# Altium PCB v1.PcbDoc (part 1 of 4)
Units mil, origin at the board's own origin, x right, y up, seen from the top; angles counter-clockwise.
Board outline 4875 x 2022 mil, 4 copper layers (Top Layer, Signal Layer 1, Signal Layer 2, Bottom Layer), stack 64.834 mil thick; 432 components, 288 nets, 1177 pads, 637 vias.
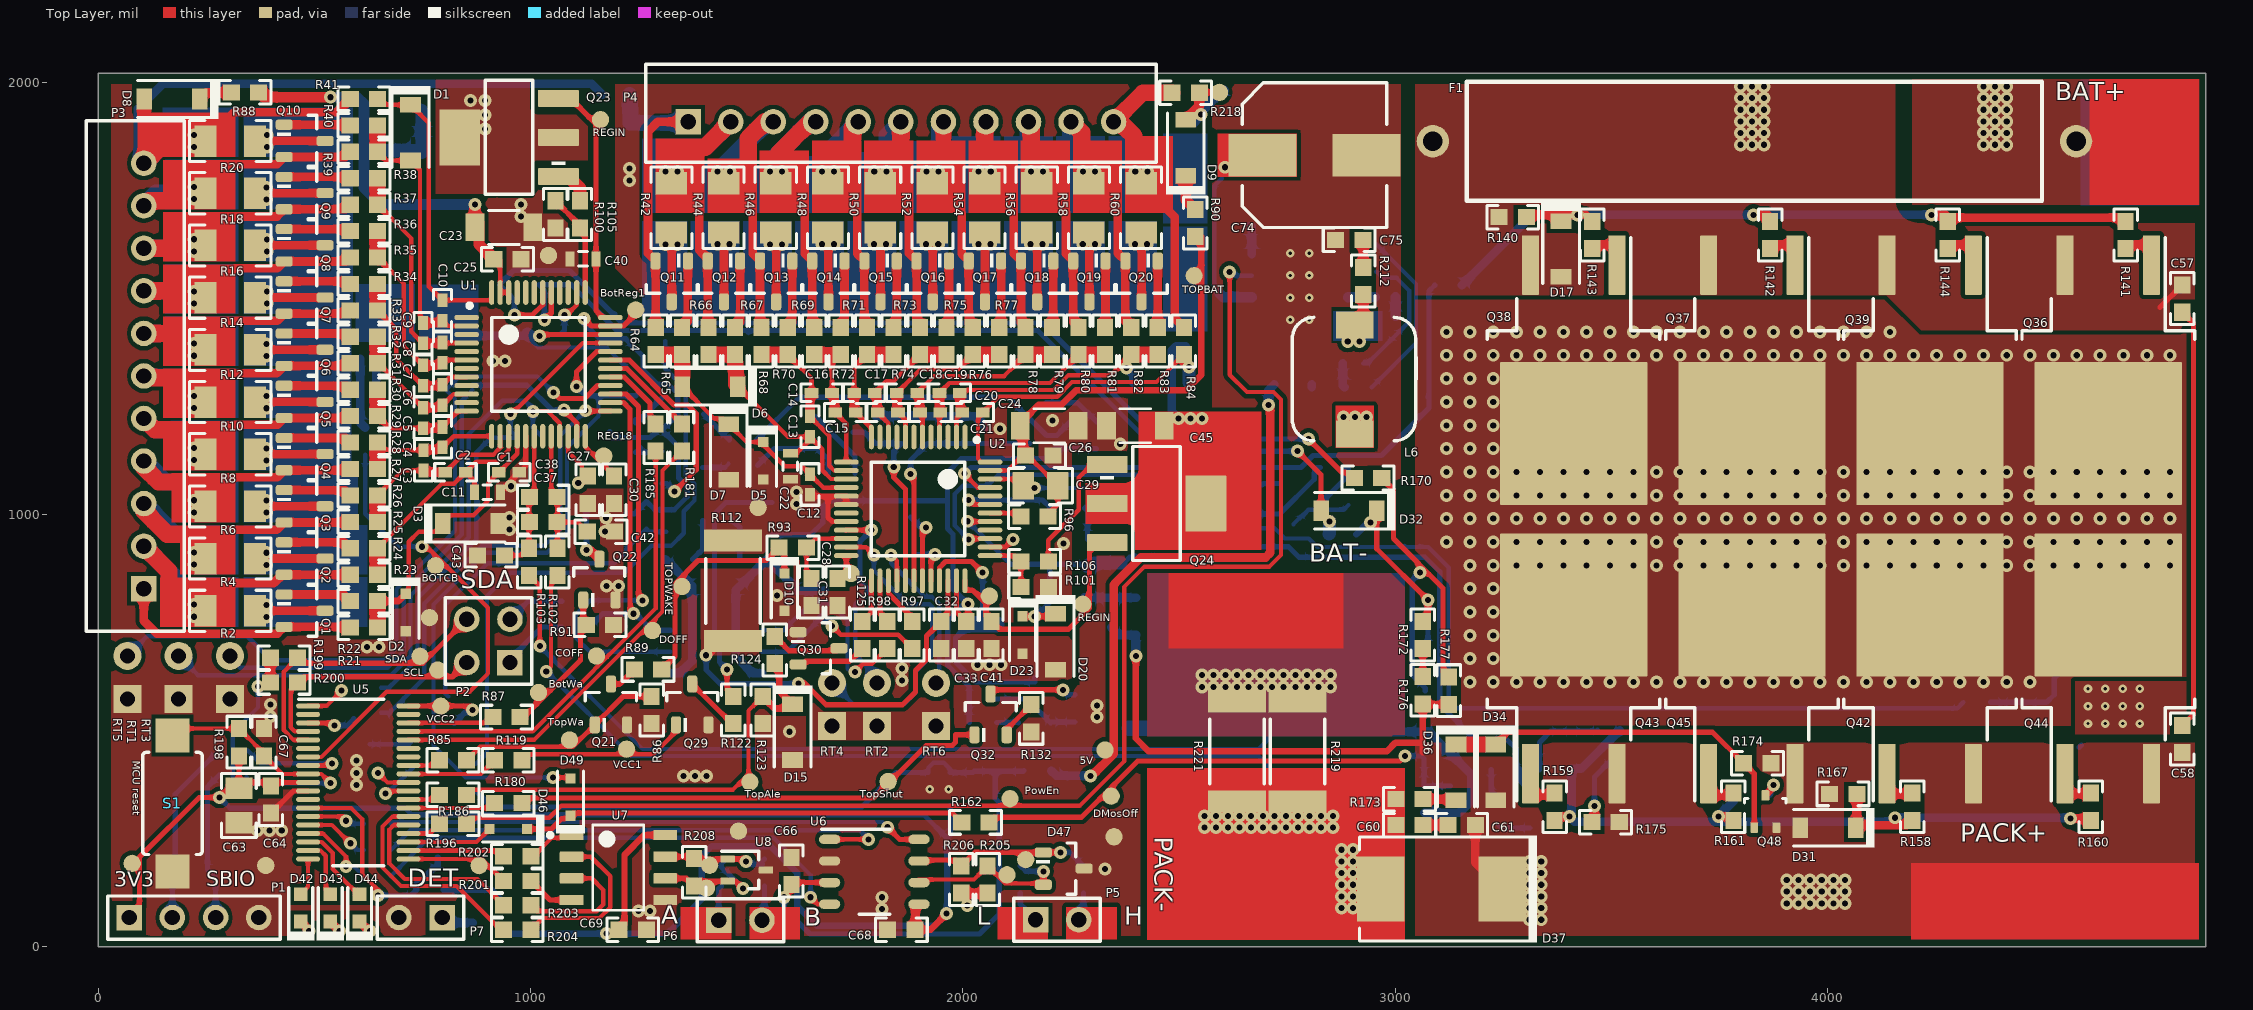
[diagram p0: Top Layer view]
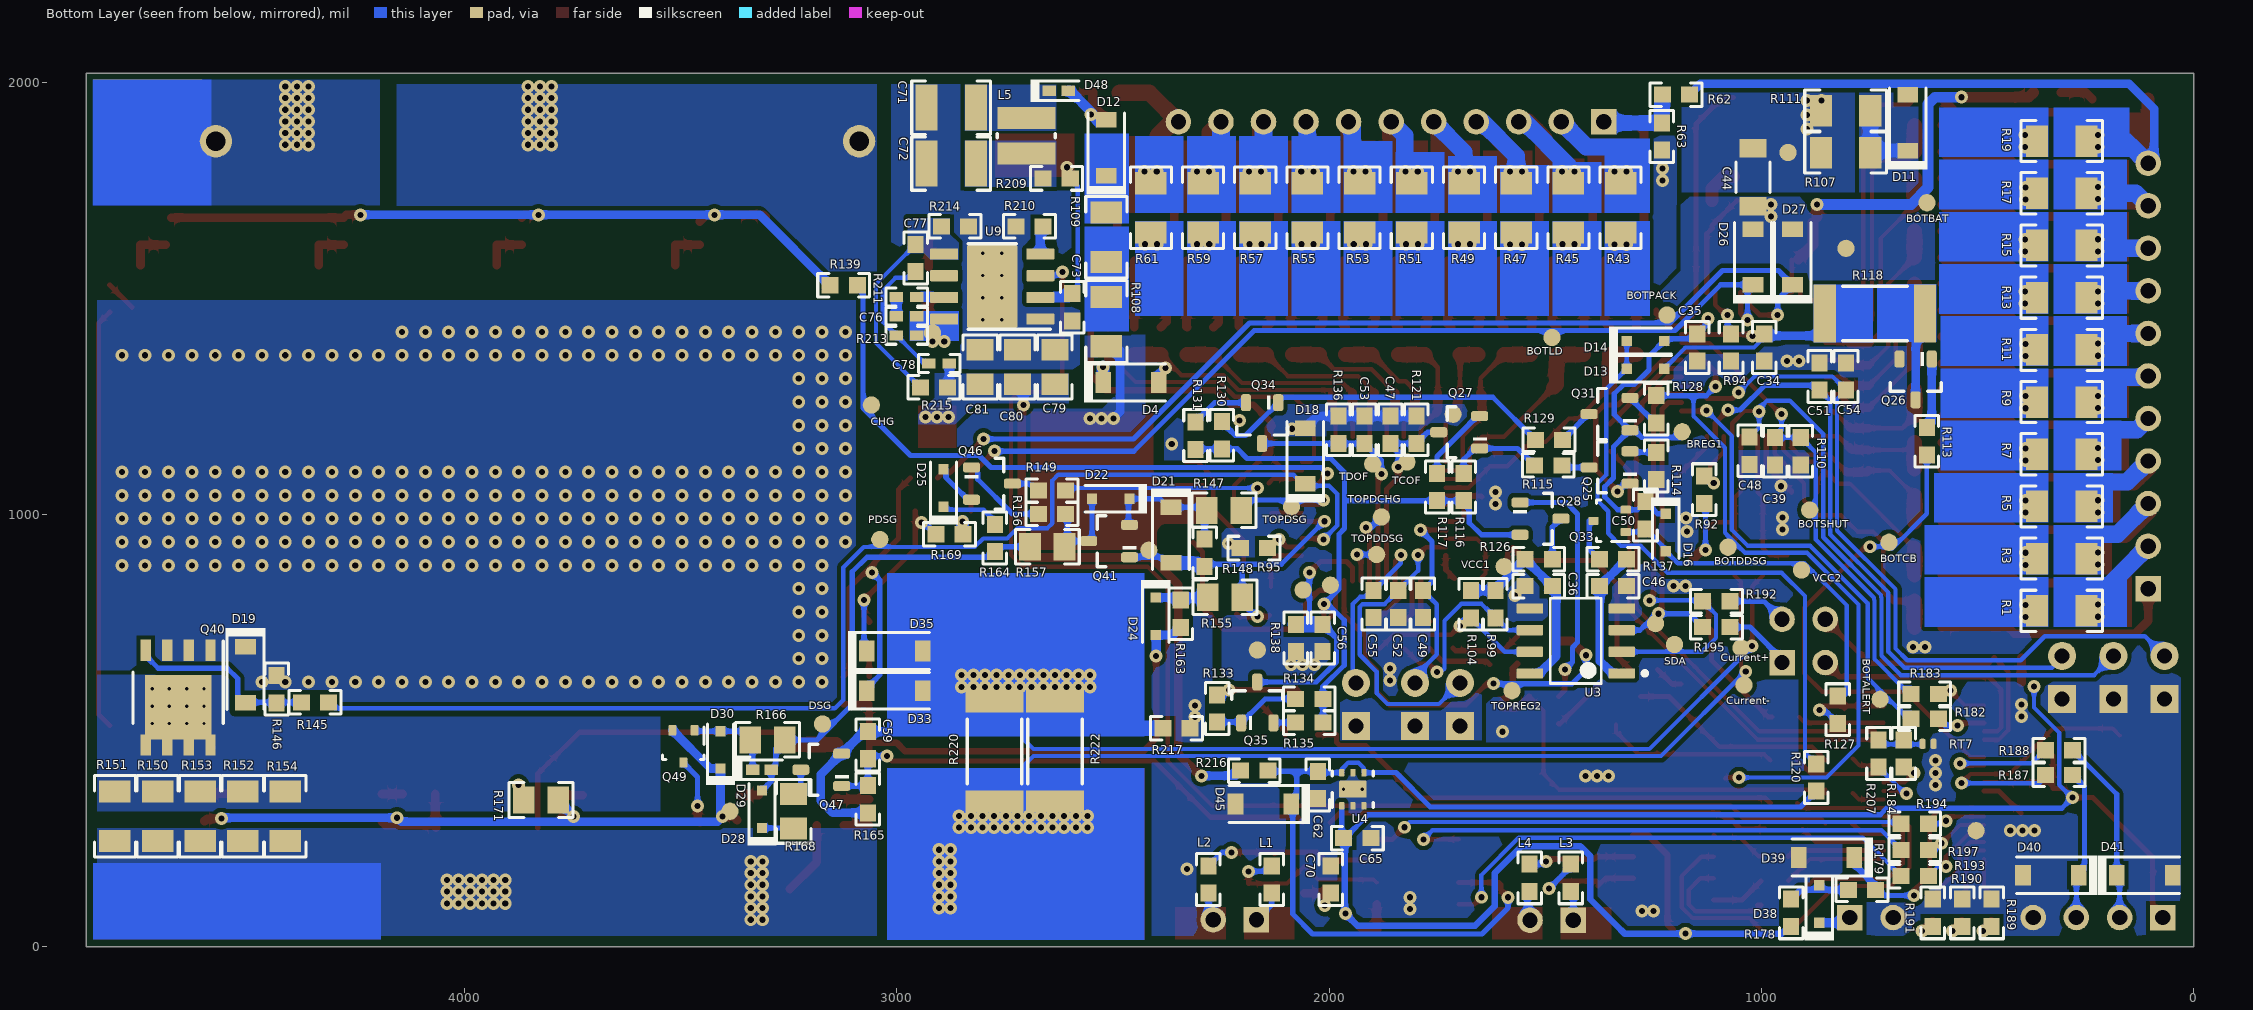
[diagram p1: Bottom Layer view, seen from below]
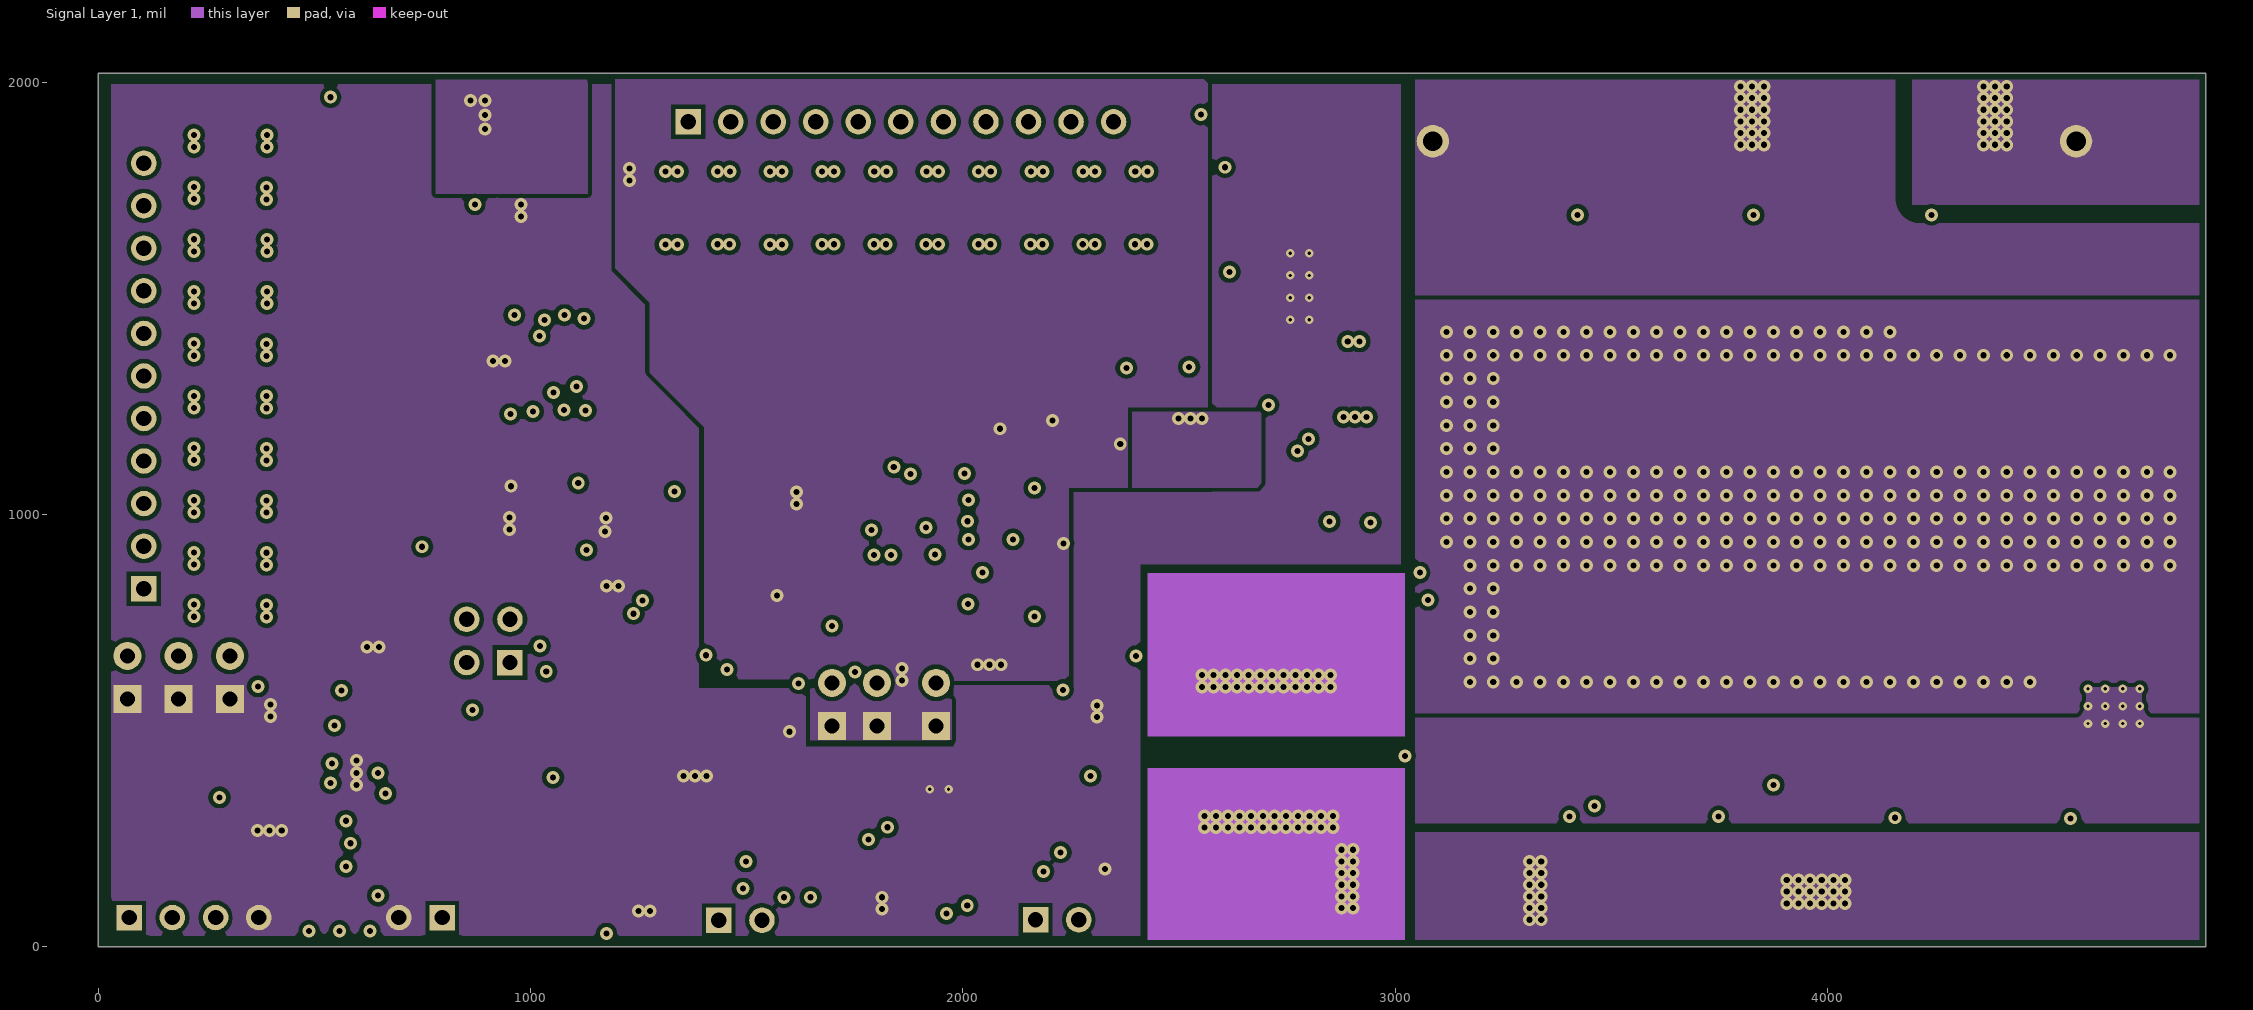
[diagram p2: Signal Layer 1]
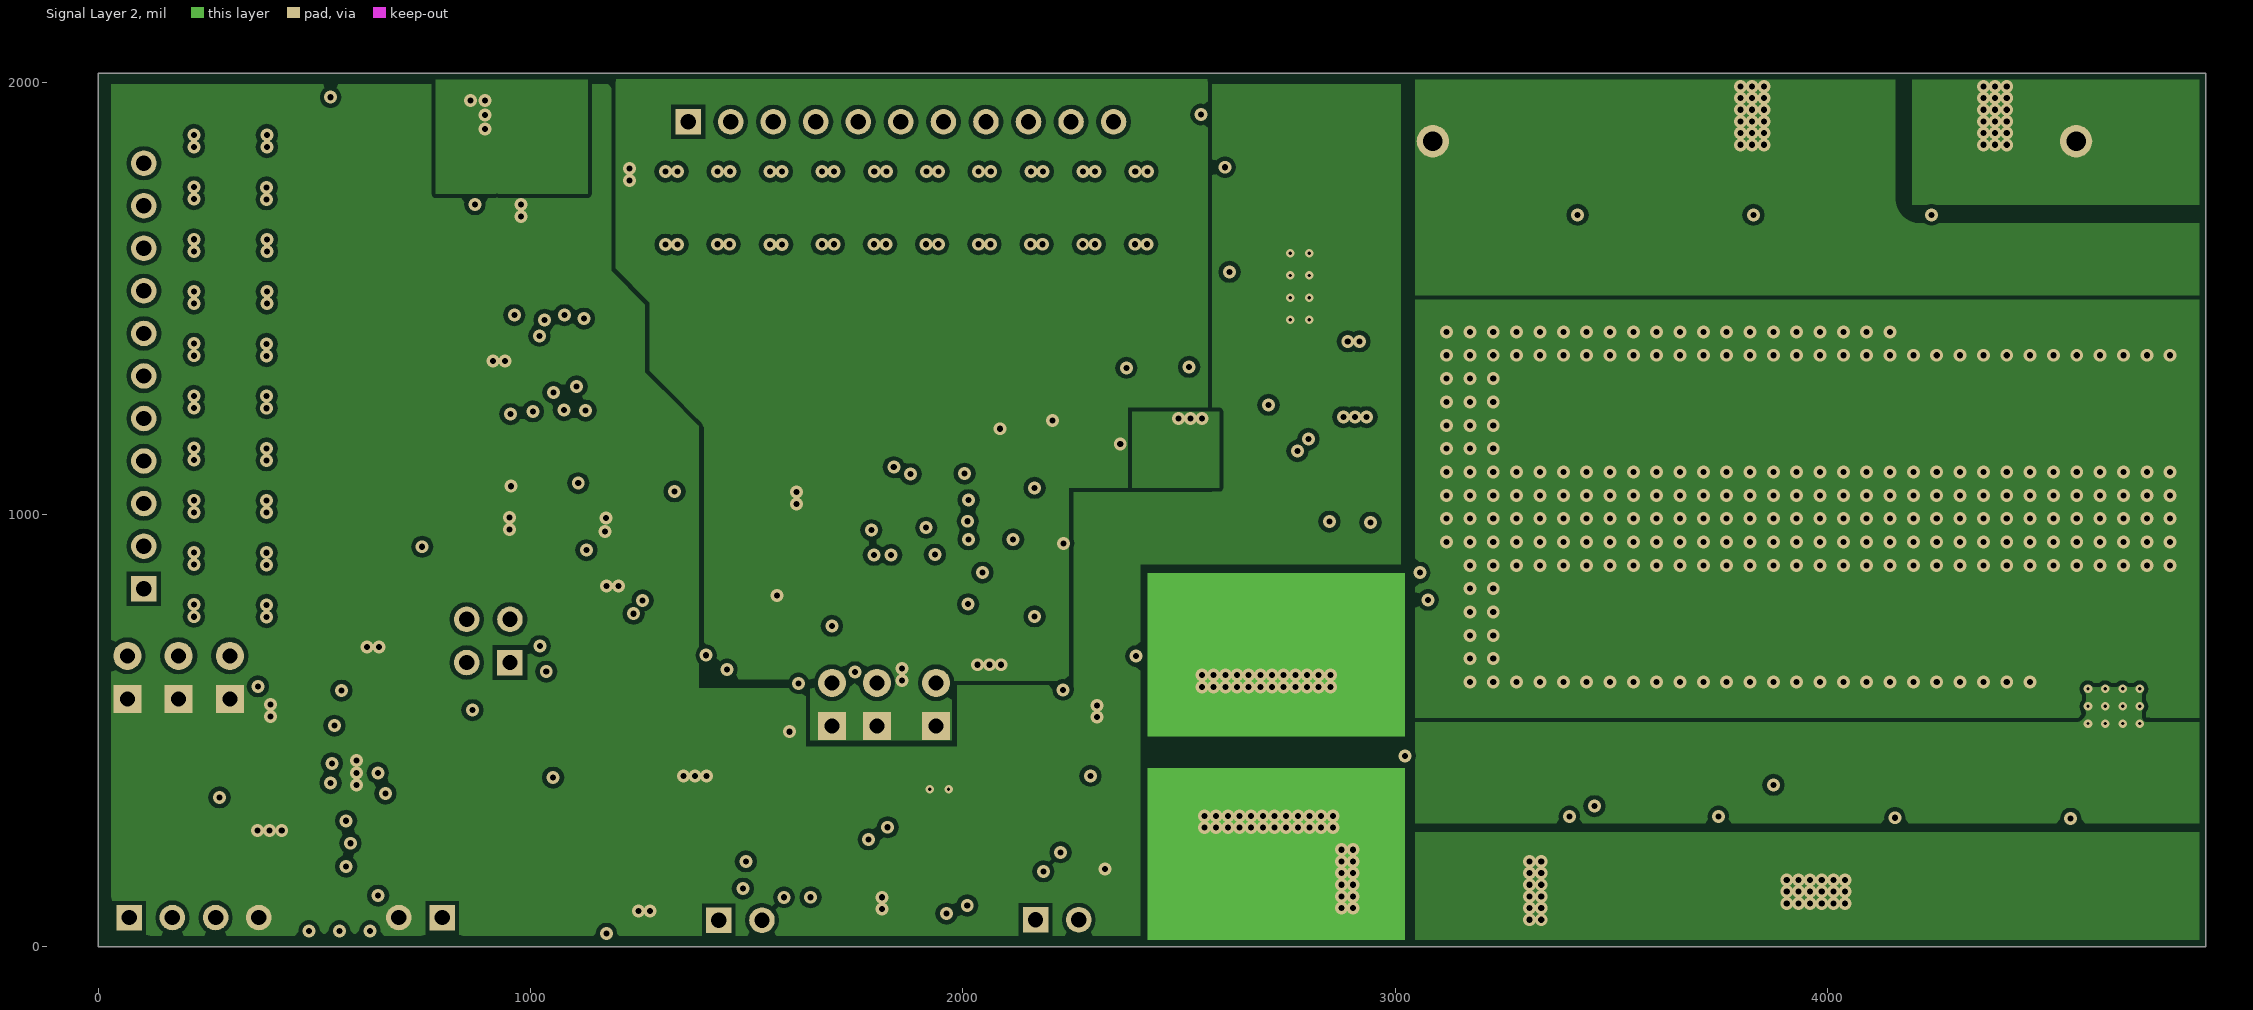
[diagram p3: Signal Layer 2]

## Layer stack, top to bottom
Top Solder: solder mask 0.4, Solder Resist, Dk 3.5
Top Layer: signal copper 1.4
Dielectric1: core 59.2, FR-4, Dk 4.8
Signal Layer 1: signal copper 1.417
Signal Layer 2: signal copper 1.417
Bottom Layer: signal copper 1.4
Bottom Solder: solder mask 0.4, Solder Resist, Dk 3.5

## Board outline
0,0 0,2022 4875,2022 4875,0

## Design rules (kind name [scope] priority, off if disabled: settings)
AcuteAngle [All] p1: minimum=4.50000000000000E+0001 checktracksonly=FALSE
AssemblyTestPointUsage [All] p1: valid=2
BoardOutlineClearance BoardOutlineClearance_MountingHoles [OnCopper and InComponentClass('Mounting Holes')] p1: gap=40 ignorepadtopadclearanceinfootprint=FALSE
BoardOutlineClearance BoardOutlineClearance_Poly [OnCopper and IsPoly] p2: gap=25 ignorepadtopadclearanceinfootprint=FALSE
BoardOutlineClearance [OnCopper and Not InComponentClass('Logo') and not InComponentClass('FiducialMark') and not InRegion(1000,500,4000,800) and not InPoly] p3 off: gap=75 ignorepadtopadclearanceinfootprint=FALSE
Clearance Clearance_Keepouts [((IsTrack Or IsArc) And Not InPoly) And IsFree and IsKeepOut vs ((IsTrack Or IsArc) And Not InPoly) And IsFree and IsKeepOut] p1: gap=0 ignorepadtopadclearanceinfootprint=FALSE
Clearance Clearance_Poly [InPolygon] p2: gap=10 ignorepadtopadclearanceinfootprint=FALSE
Clearance Clearance_FiducialMark [IsKeepOut and InComponentClass('FiducialMark') vs IsPad and InComponentClass('FiducialMark')] p3: gap=0 ignorepadtopadclearanceinfootprint=FALSE
Clearance [All] p4: gap=6 ignorepadtopadclearanceinfootprint=FALSE
ComponentClearance ComponentClearance_MountingHoles_FiducialMarks [InComponentClass('Mounting Holes') vs InComponentClass('FiducialMark')] p1: gap=0 collisioncheckmode=3 verticalgap=10 showdistances=FALSE
ComponentClearance ComponentClearance_Shunt [InComponentClass('Header') vs InComponentClass('Shunt')] p2: gap=0 collisioncheckmode=3 verticalgap=0 showdistances=FALSE
ComponentClearance ComponentClearance_Logo [InComponentClass('Logo')] p3: gap=50 collisioncheckmode=3 verticalgap=10 showdistances=FALSE
ComponentClearance ComponentClearance_ScrewToNut [(HasFootprint('NY PMS 440 0025 PH')) vs (HasFootprint('Keystone_1902C'))] p4: gap=5 collisioncheckmode=3 verticalgap=10 showdistances=FALSE
ComponentClearance ComponentClearance_MountingHoles [InComponentClass('Mounting Holes')] p5: gap=6 collisioncheckmode=3 verticalgap=100000 showdistances=FALSE
ComponentClearance ComponentClearance_SmallPassives [HasFootprint('0201*') or HasFootprint('0402*') or HasFootprint('0508') or HasFootprint('0603*') or HasFootprint('0612') or HasFootprint('0805*') or HasFootprint('0815*') or HasFootprint('0830*') or HasFootprint('1206*') or HasFootprint('1210*') or HasFootprint('1808*') or HasFootprint('1812*') or HasFootprint('1825*') or HasFootprint('2010*') or HasFootprint('2220*') or HasFootprint('2225*') or HasFootprint('2512*') or HasFootprint('2728*') or HasFootprint('3518*') vs HasFootprint('0201*') or HasFootprint('0402*') or HasFootprint('0508') or HasFootprint('0603*') or HasFootprint('0612') or HasFootprint('0805*') or HasFootprint('0815*') or HasFootprint('0830*') or HasFootprint('1206*') or HasFootprint('1210*') or HasFootprint('1808*') or HasFootprint('1812*') or HasFootprint('1825*') or HasFootprint('2010*') or HasFootprint('2220*') or HasFootprint('2225*') or HasFootprint('2512*') or HasFootprint('2728*') or HasFootprint('3518*')] p6: gap=6 collisioncheckmode=3 verticalgap=10 showdistances=FALSE
ComponentClearance ComponentClearance_THtoSMT [IsThruComponent vs IsSMTComponent] p7: gap=6 collisioncheckmode=3 verticalgap=30 showdistances=FALSE
ComponentClearance ComponentClearance_THtoTH [IsThruComponent vs IsThruComponent] p8: gap=0 collisioncheckmode=3 verticalgap=30 showdistances=FALSE
ComponentClearance [All] p9: gap=0 collisioncheckmode=3 verticalgap=100000 showdistances=FALSE
DiffPairsRouting [All] p1: maxlimit=100 minlimit=10 mostfreqgap=10 substack1={15AE82B9-5E42-45CF-8A33-7C54FC62AE9B} toplayer_{15ae82b9-5e42-45cf-8a33-7c54fc62ae9b}_minwidth=15 toplayer_{15ae82b9-5e42-45cf-8a33-7c54fc62ae9b}_maxwidth=15 toplayer_{15ae82b9-5e42-45cf-8a33-7c54fc62ae9b}_prefwidth=15 midlayer1_{15ae82b9-5e42-45cf-8a33-7c54fc62ae9b}_minwidth=15 midlayer1_{15ae82b9-5e42-45cf-8a33-7c54fc62ae9b}_maxwidth=15 midlayer1_{15ae82b9-5e42-45cf-8a33-7c54fc62ae9b}_prefwidth=15 midlayer2_{15ae82b9-5e42-45cf-8a33-7c54fc62ae9b}_minwidth=15 midlayer2_{15ae82b9-5e42-45cf-8a33-7c54fc62ae9b}_maxwidth=15 midlayer2_{15ae82b9-5e42-45cf-8a33-7c54fc62ae9b}_prefwidth=15 bottomlayer_{15ae82b9-5e42-45cf-8a33-7c54fc62ae9b}_minwidth=15 bottomlayer_{15ae82b9-5e42-45cf-8a33-7c54fc62ae9b}_maxwidth=15 bottomlayer_{15ae82b9-5e42-45cf-8a33-7c54fc62ae9b}_prefwidth=15 toplayer_minwidth=15 toplayer_maxwidth=15 toplayer_prefwidth=15 midlayer1_minwidth=15 midlayer1_maxwidth=15 midlayer1_prefwidth=15 midlayer2_minwidth=15 midlayer2_maxwidth=15 midlayer2_prefwidth=15 bottomlayer_minwidth=15 bottomlayer_maxwidth=15 bottomlayer_prefwidth=15 maxuncoupledlength=1000
FabricationTestPointUsage TestPointUsage [All] p1: valid=2 allowmultiple=FALSE
FabricationTestpoint Testpoint [All] p1: side=3 testpointundercomponent=TRUE minsize=40 maxsize=100 preferedsize=60 minholesize=0 maxholesize=40 preferedholesize=32 testpointgrid=1 allowsidetop=TRUE allowsidebottom=TRUE usegrid=TRUE gridtolerance=0.01
FanoutControl Fanout_LCC [IsLCC] p1: bgadir=Out bgaviamode=Centered fanoutstyle=Auto fanoutdirection=Alternating viagrid=1 // Fanout_LCC (Default Rule)
FanoutControl Fanout_BGA [IsBGA] p2: bgadir=Out bgaviamode=Centered fanoutstyle=Auto fanoutdirection=Alternating viagrid=1 // Fanout_BGA (Default Rule)
FanoutControl Fanout_Default [All] p4: bgadir=Out bgaviamode=Centered fanoutstyle=Auto fanoutdirection=Alternating viagrid=1 // Fanout_Default (Default Rule)
FanoutControl Fanout_Small [(CompPinCount < 5)] p5: bgadir=Out bgaviamode=Centered fanoutstyle=Auto fanoutdirection=OutThenIn viagrid=1 // Fanout_Small (Default Rule)
HoleSize [All] p1: absolutevalues=TRUE maxlimit=251 minlimit=7.87 maxpercent=80.000 minpercent=20.000
MinimumAnnularRing MinimumAnnularRing_ThermalPadVias [IsVia and InAnyComponent] p1: minimumring=5.91
MinimumAnnularRing [All] p2: minimumring=8
MinimumSolderMaskSliver MinimumSolderMaskSliver_Logo [InComponentClass('Logo') vs InComponentClass('Logo')] p1 off: minsoldermaskwidth=0.7
MinimumSolderMaskSliver [All] p2 off: minsoldermaskwidth=3.94
PlaneConnect [All] p1: planeconnectstyle=Relief reliefexpansion=10 reliefentries=4 reliefconductorwidth=10 reliefairgap=10
PolygonConnect [All] p1: connectstyle=Direct reliefconductorwidth=10 reliefentries=4 polygonreliefangle="90 Angle" airgapwidth=10
RoutingVias ThermalPadVias [IsVia and InAnyComponent] p1: holewidth=7.87 width=19.68 viastyle="Through Hole" minholewidth=7.87 minwidth=19.68 maxholewidth=12.99 maxwidth=23.62
RoutingVias [All] p2: holewidth=16 width=34 viastyle="Through Hole" minholewidth=7.87 minwidth=26 maxholewidth=40 maxwidth=65
SilkToBoardRegionClearance [Not ((IsComment or IsDesignator) And (Hide <> 'False')) and not InRegion(1000,500,4000,800)] p1:
SilkToSilkClearance SilkToSilkClearance_Pb-FreeLogo [(HasFootprint('Pb-Free_Overlay_Medium') OR HasFootprint('Pb-Free_Overlay_Small')) vs (HasFootprint('Pb-Free_Overlay_Medium') OR HasFootprint('Pb-Free_Overlay_Small'))] p1 off: silktosilkclearance=0
SilkToSilkClearance [All] p2 off: silktosilkclearance=4
SilkToSolderMaskClearance SilkToComponentPadClearance [(IsPad or IsFill or IsRegion) and InAnycomponent] p1 off: minsilkscreentomaskgap=5 clearancetoexposedcopper=TRUE
SilkToSolderMaskClearance "Silk to Solder Mask Opening" [All] p2 off: minsilkscreentomaskgap=4 clearancetoexposedcopper=FALSE
SolderMaskExpansion [All] p1: expansion=1.97 istentingtop=FALSE
Width [All] p1: maxlimit=100 minlimit=6 preferedwidth=10 substack1={15AE82B9-5E42-45CF-8A33-7C54FC62AE9B} checkconnectedcopper=TRUE
15 further rules are at their usual default settings.

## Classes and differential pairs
component class "High level sch": D49 P3 P4 P5 P6 P7 R217 R218 R219 R220 R221 R222
component class Designator: C62 C63 C64 C65 C66 C67 C68 C69 C70 D38 D39 D40 D41 D42 D43 D44 D45 D46 D47 L1 L2 L3 L4 P1 P2 R178 R179 R180 R181 R182 R183 R184 R185 R186 R187 R188 R189 R190 R191 R192 R193 R194 R195 R196 R197 R198 R199 R200 R201 R202 R203 R204 R205 R206 R207 R208 RT7 S1 U4 U5 U6 U7 U8
component class Designator: C1 C2 C3 C4 C5 C6 C7 C8 C9 C10 C11 C12 C13 C14 C15 C16 C17 C18 C19 C20 C21 C22 C23 C24 C25 C26 C27 C28 C29 C30 C31 C32 C33 C34 C35 C36 C37 C38 C39 C40 C41 C42 C43 C44 C45 C46 C47 C48 C49 C50 C51 C52 C53 C54 C55 C56 D1 D2 D3 D4 D5 D6 D7 D8 D9 D10 D11 D12 D13 D14 D15 D16 Q1 Q2 Q3 Q4 Q5 Q6 Q7 Q8 Q9 Q10 Q11 Q12 Q13 Q14 Q15 Q16 Q17 Q18 Q19 Q20 Q21 Q22 Q23 Q24 Q25 Q26 Q27 Q28 Q29 Q30 Q31 Q32 Q33 Q34 Q35 Q50 R1 R2 R3 R4 R5 R6 R7 R8 R9 R10 R11 R12 R13 R14 R15 R16 R17 R18 R19 R20 R21 R22 R23 R24 R25 R26 R27 R28 R29 R30 R31 R32 R33 R34 R35 R36 R37 R38 R39 R40 R41 R42 R43 R44 R45 R46 R47 R48 R49 R50 R51 R52 R53 R54 R55 R56 R57 R58 R59 R60 R61 R62 R63 R64 R65 R66 R67 R68 R69 R70 R71 R72 R73 R74 R75 R76 R77 R78 R79 R80 R81 R82 R83 R84 R85 R86 R87 R88 R89 R90 R91 R92 R93 R94 R95 R96 R97 R98 R99 R100 R101 R102 R103 R104 R105 R106 R107 R108 R109 R110 R111 R112 R113 R114 R115 R116 R117 R118 R119 R120 R121 R122 R123 R124 R125 R126 R127 R128 R129 R130 R131 R132 R133 R134 R135 R136 R137 R138 RT1 RT2 RT3 RT4 RT5 RT6 U1 U2 U3

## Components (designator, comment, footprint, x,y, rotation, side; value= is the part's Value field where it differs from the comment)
C1 "GRM155R71E104KE14D" 0402 950,1098.5 r0 top value=0.1uF
C2 "GRM155R71E104KE14D" 0402 826,1098.5 r0 top value=0.1uF
C3 "GRM155R71E104KE14D" 0402 752,1126 r270 top value=0.1uF
C4 "GRM155R71E104KE14D" 0402 796,1179.38 r270 top value=0.1uF
C5 "GRM155R71E104KE14D" 0402 751,1224 r270 top value=0.1uF
C6 "GRM155R71E104KE14D" 0402 796,1277.13 r270 top value=0.1uF
C7 "GRM155R71E104KE14D" 0402 751,1322 r270 top value=0.1uF
C8 "GRM155R71E104KE14D" 0402 796,1374.87 r270 top value=0.1uF
C9 "GRM155R71E104KE14D" 0402 751,1420 r270 top value=0.1uF
C10 "GRM155R71E104KE14D" 0402 796,1472.62 r270 top value=0.1uF
C11 "GRM188R71H104KA93D" 0603S 900,1052 r0 top value=0.1uF
C12 "GRM155R71E104KE14D" 0402 1646,1070 r270 top value=0.1uF
C13 "GRM155R71E104KE14D" 0402 1646,1204 r270 top value=0.1uF
C14 "GRM155R71E104KE14D" 0402 1673.38,1282 r180 top value=0.1uF
C15 "GRM155R71E104KE14D" 0402 1728,1236.7 r180 top value=0.1uF
C16 "GRM155R71E104KE14D" 0402 1772.04,1282 r180 top value=0.1uF
C17 "GRM155R71E104KE14D" 0402 1826.13,1236.7 r180 top value=0.1uF
C18 "GRM155R71E104KE14D" 0402 1870.71,1282 r180 top value=0.1uF
C19 "GRM155R71E104KE14D" 0402 1924.25,1236.7 r180 top value=0.1uF
C20 "GRM155R71E104KE14D" 0402 1969.38,1282 r180 top value=0.1uF
C21 "GRM155R71E104KE14D" 0402 2022.38,1236.7 r180 top value=0.1uF
C22 "GRM188R71H104KA93D" 0603S 1601,1112 r270 top value=0.1uF
C23 "C1206X225K101TX" 1206_190 938,1665 r180 top value=2.2uF
C24 "C1206X225K101TX" 1206_190 2199.8,1205.97 r180 top value=2.2uF
C25 "GRM1885C2A101JA01D" 0603 946,1591 r180 top value=100pF
C26 "GRM1885C2A101JA01D" 0603 2176.8,1136.97 r180 top value=100pF
C27 "GRM1885C2A101JA01D" 0603 1132,1057.87 r270 top value=100pF
C28 "GRM1885C2A101JA01D" 0603 1649.54,821 r270 top value=100pF
C29 "GRM21BR71E225KA73L" 0805_HV 2179.8,1066.97 r0 top value=2.2uF
C30 "EMK107BB7225MA-T" 0603 1193,1057.87 r270 top value=2.2uF
C31 "EMK107BB7225MA-T" 0603 1709.92,821 r270 top value=2.2uF
C32 "GCM188R71C105KA64D" 0603 1949.85,721.65 r270 top value=1uF
C33 "GCM188R71C105KA64D" 0603 2007.82,721.65 r270 top value=1uF
C34 "GCM188R71C105KA64D" 0603 993,1387 r270 bottom value=1uF
C35 "GCM188R71C105KA64D" 0603 1148,1387 r270 bottom value=1uF
C36 "GRM188R71H104KA93D" 0603 1515,834.93 r0 bottom value=0.1uF
C37 "GRM188R71H104KA93D" 0603 1029,983 r0 top value=0.1uF
C38 "GRM1885C2A101JA01D" 0603 1029,1041 r0 top value=100pF
C39 "GRM1885C2A101JA01D" 0603 968.27,1147 r270 bottom value=100pF
C40 "GRM188R71H223KA01D" 0603S 1121,1592 r180 top value=0.022uF
C41 "GRM188R71H223KA01D" 0603 2065.8,721.65 r270 top value=0.022uF
C42 "GRM188R71H104KA93D" 0603 1162.33,961.07 r0 top value=0.1uF
C43 "GRM188R71H104KA93D" 0603 908,906 r0 top value=0.1uF
C44 "C3216X7R2A105K160AA" 1206_180 1019,1780.93 r270 bottom value=1uF
C45 "C3216X7R2A105K160AA" 1206_180 2399,1205.97 r180 top value=1uF
C46 "GRM188R71H104KA93D" 0603 1343,835 r180 bottom value=0.1uF
C47 "GRM1885C1H470JA01D" 0603 1858.03,1196.65 r90 bottom value=47pF
C48 "GRM188R71H471KA01D" 0603 1027,1148 r270 bottom value=470pF
C49 "GRM188R71H471KA01D" 0603 1783,793.27 r270 bottom value=470pF
C50 "GRM1885C2A101JA01D" 0603 1268,999 r270 bottom value=100pF
C51 "GRM188R71H471KA01D" 0603 865,1320 r90 bottom value=470pF
C52 "GRM188R71H471KA01D" 0603 1840,793.27 r270 bottom value=470pF
C53 "GRM1885C1H470JA01D" 0603 1918.13,1196.65 r90 bottom value=47pF
C54 "GRM188R71H471KA01D" 0603 804,1320 r90 bottom value=470pF
C55 "GRM188R71H471KA01D" 0603 1897,793.27 r270 bottom value=470pF
C56 "GRM1885C1H470JA01D" 0603 2014.87,715 r270 bottom value=47pF
C57 "GRM188R72A104KA35D" 0603 4821,1500 r90 top value=0.1uF
C58 "GRM188R72A104KA35D" 0603 4821,481 r90 top value=0.1uF
C59 "GRM1885C2A101JA01D" 0603 3067,467 r90 bottom value=100pF
C60 "GRM188R72A104KA35D" 0603 3033,282 r180 top value=0.1uF
C61 "GRM188R72A104KA35D" 0603 3154,282 r180 top value=0.1uF
C62 "GCM188R71C105KA64D" 0603 2026,375 r270 bottom value=1uF
C63 "C2012X6S1C106K085AC" 0805_HV 325,327 r90 top value=10uF
C64 "GRM188R71H104KA93D" 0603 399,341.02 r90 top value=0.1uF
C65 "EMK107BB7225MA-T" 0603 1934.62,252 r180 bottom value=2.2uF
C66 "GRM188R71H104KA93D" 0603 1603,176 r90 top value=0.1uF
C67 "GRM1885C1H102JA01D" 0603 383,473.85 r90 top value=1000pF
C68 "GRM188R71H104KA93D" 0603 1857.5,40 r180 top value=0.1uF
C69 "GRM188R71H104KA93D" 0603 1236,39.93 r0 top value=0.1uF
C70 "GRM188R71H104KA93D" 0603 1996.07,156 r270 bottom value=0.1uF
C71 "C3225X7S2A475K200AE" 1210 2874.33,1942 r0 bottom value=4.7uF
C72 "C3225X7S2A475K200AE" 1210 2874.33,1812.52 r0 bottom value=4.7uF
C73 "GRM188R72A104KA35D" 0603 2594.33,1480 r270 bottom value=0.1uF
C74 "UUX2A100MNL1GS" UUX_800x620 2813.41,1832 r0 top value=10uF
C75 "GRM1885C1H560JA01D" 0603 2893.62,1636 r180 top value=NC
C76 "GRM155R71H222KA01D" 0402 2977.33,1459.5 r180 bottom value=2200pF
C77 "GRM1885C2A101JA01D" 0603 2956.53,1594 r90 bottom value=100pF
C78 "GRM155R71H152KA01D" 0402 2902.35,1350 r0 bottom value=1500pF
C79 "GRM21BR71C475KA73L" 0805_HV 2634.33,1341.5 r90 bottom value=4.7uF
C80 "GRM21BR71C475KA73L" 0805_HV 2720.83,1341.5 r90 bottom value=4.7uF
C81 "GRM21BR71C475KA73L" 0805_HV 2807.33,1341.5 r90 bottom value=4.7uF
D1 "BAT46W-7-F" SOD-123 722,1884 r270 top value=100V
D2 "BAT42WS-7-F" SOD-323 711,774 r270 top value=30V
D3 "MMSZ4685T1G" SOD-123 861,980 r0 top value=3.6V
D4 "BAT46W-7-F" SOD-123 2458.47,1306 r180 bottom value=100V
D5 "BAT42WS-7-F" SOD-323 1538,1125 r270 top value=30V
D6 "BAT46W-7-F" SOD-123 1415,1296 r180 top value=100V
D7 "MMSZ4685T1G" SOD-123 1458,1145 r270 top value=3.6V
D8 "BAT46W-7-F" SOD-123 170,1962 r180 top value=100V
D9 "BAT46W-7-F" SOD-123 2515.33,1849 r90 top value=100V
D10 "BAT42WS-7-F" SOD-323 1587.06,821.06 r270 top value=30V
D11 "BAT46W-7-F" SOD-123 661,1907 r90 bottom value=100V
D12 "BAT46W-7-F" SOD-123 2515.33,1849 r90 bottom value=100V
D13 "DB2J20900L" SOD-323F 1268,1338 r180 bottom value=20V
D14 "DB2J20900L" SOD-323F 1268,1402 r180 bottom value=20V
D15 "MMSZ4685T1G" SOD-123 1606,497 r270 top value=3.6V
D16 "NC" SOD-323 1221.19,959 r270 bottom value=30V
D17 "MMSZ5246B-7-F" SOD-123 3384,1615 r270 top value=16V
D18 "MMSZ5267BT1G" SOD-123 2055,1136 r90 bottom value=75V
D19 "MMSZ5246B-7-F" SOD-123 4507,630 r270 bottom value=16V
D20 "MMSZ5267BT1G" SOD-123 2214,706 r270 top value=75V
D21 "MMSZ5246B-7-F" SOD-123 2366,953 r270 bottom value=16V
D22 "NC" SOD-323F 2505,1037 r0 bottom value=100V
D23 "BAT46WJ,115" SOD-323F 2138,721.71 r270 top value=100V
D24 "BAT46WJ,115" SOD-323F 2401,765 r270 bottom value=100V
D25 "BAT46WJ,115" SOD-323F 2892,1062 r90 bottom value=100V
D26 "MMSZ5267BT1G" SOD-123 1019,1596.52 r90 bottom value=75V
D27 "MMSZ5267BT1G" SOD-123 927.55,1596.52 r90 bottom value=75V
D28 "BAT46WJ,115" SOD-323F 3312,318.52 r90 bottom value=100V
D29 "BAS516,115" SOD-523 3312,410 r180 bottom value=100V
D30 "BZT52C5V1S-7-F" SOD-323 3408,456 r90 bottom value=5.1V
D31 "MMSZ5246B-7-F" SOD-123 4001.53,276 r180 top value=16V
D32 "BAT46W-7-F" SOD-123 2893,1009 r180 top value=100V
D33 "BAT46W-7-F" SOD-123 3005,593 r180 bottom value=100V
D34 "MMSZ5246B-7-F" SOD-123 3233,404 r270 top value=16V
D35 "BAT46W-7-F" SOD-123 3005,685 r180 bottom value=100V
D36 "BAT46W-7-F" SOD-123 3141,404 r270 top value=100V
D37 "ES3D-E3/57T" SMC 3107,134 r180 top value=200V
D38 "BAT46WJ,115" SOD-323F 866,99.52 r90 bottom value=100V
D39 "MMSZ4685T1G" SOD-123 849,207 r0 bottom value=NC
D40 "MMSZ4685T1G" SOD-123 330,166 r0 bottom value=3.6V
D41 "MMSZ4685T1G" SOD-123 113,166 r180 bottom value=3.6V
D42 "150060RS75000" WL-SMCW_RED 468,90.32 r90 top value=Red
D43 "150060RS75000" WL-SMCW_RED 536,90.32 r90 top value=Red
D44 "150060RS75000" WL-SMCW_RED 604,90.32 r90 top value=Red
D45 "MMSZ4690T1G" SOD-123 2152.03,331 r0 bottom value=5.6V
D46 "DB2J20900L" SOD-323F 948,273 r180 top value=20V
D47 "NUP3105LT1G" SOT-23 2233.24,181.4 r0 top value=24V
D48 "BAS516,115" SOD-523 2625.33,1981.22 r180 bottom value=100V
D49 "DB2J20900L" SOD-323F 1092,346.69 r90 top value=20V
F1 "0325030.HXP" 0325030 3166,2002 r0 top
L1 "74279265" 0603 2132.76,156 r90 bottom value="600 ohm"
L2 "74279265" 0603 2279.17,156 r90 bottom value="600 ohm"
L3 "74279265" 0603 1441,160 r90 bottom value="600 ohm"
L4 "74279265" 0603 1536,160 r90 bottom value="600 ohm"
L5 "74438335010" WE-MAPI_3015 2700.33,1877 r270 bottom value=1uH
L6 "744777168" WE-PD_7345 2906.7,1313 r270 top value=68uH
P1 "Header 4" HDR1X4 71,68 r0 top
P2 "Header 2X2" HDR2X2 952,658 r90 top
P3 "Header 11" "XH Connector 11P" 105,829 r180 top
P4 "Header 11" "XH Connector 11P" 1364.33,1909 r90 top
P5 "Header 2" HDR1X2 2168,63 r0 top
P6 "Header 2" HDR1X2 1435,62 r0 top
P7 "Header 2" HDR1X2 795,68 r180 top
Q1 "BSR14" SOT-23 477,778 r0 top value="40 V"
Q2 "BSR14" SOT-23 477,898.78 r0 top value="40 V"
Q3 "BSR14" SOT-23 477,1019.56 r0 top value="40 V"
Q4 "BSR14" SOT-23 477,1140.33 r0 top value="40 V"
Q5 "BSR14" SOT-23 477,1261.11 r0 top value="40 V"
Q6 "BSR14" SOT-23 477,1381.89 r0 top value="40 V"
Q7 "BSR14" SOT-23 477,1502.67 r0 top value="40 V"
Q8 "BSR14" SOT-23 477,1623.44 r0 top value="40 V"
Q9 "BSR14" SOT-23 477,1744.22 r0 top value="40 V"
Q10 "BSR14" SOT-23 477,1865 r0 top value="40 V"
Q11 "BSR14" SOT-23 1326.33,1540 r270 top value="40 V"
Q12 "BSR14" SOT-23 1447.11,1540 r270 top value="40 V"
Q13 "BSR14" SOT-23 1567.89,1540 r270 top value="40 V"
Q14 "BSR14" SOT-23 1688.66,1540 r270 top value="40 V"
Q15 "BSR14" SOT-23 1809.44,1540 r270 top value="40 V"
Q16 "BSR14" SOT-23 1930.22,1540 r270 top value="40 V"
Q17 "BSR14" SOT-23 2051,1540 r270 top value="40 V"
Q18 "BSR14" SOT-23 2171.78,1540 r270 top value="40 V"
Q19 "BSR14" SOT-23 2292.55,1540 r270 top value="40 V"
Q20 "BSR14" SOT-23 2413.33,1540 r270 top value="40 V"
Q21 "BC846B,215" SOT-23 1185.7,561.29 r90 top value="65 V"
Q22 "MMBTA05LT1G" SOT-23 1159,850 r90 top value="60 V"
Q23 "FZT493ATA" SOT-223 950,1873 r180 top value=60V
Q24 "FZT493ATA" SOT-223 2448,1026 r0 top value=60V
Q25 "MMBTA05LT1G" SOT-23 1351,1109.5 r0 bottom value="60 V"
Q26 "MMBTA05LT1G" SOT-23 643,1313 r270 bottom value="60 V"
Q27 "MMBTA56LT1G" SOT-23 1699,1191 r0 bottom value="80 V"
Q28 "MMBTA56LT1G" SOT-23 1510.76,991 r180 bottom value="80 V"
Q29 "MMBTA05LT1G" SOT-23 1373.7,561.29 r90 top value="60 V"
Q30 "MMBTA56LT1G" SOT-23 1666,691 r0 top value="80 V"
Q31 "MMBTA05LT1G" SOT-23 1351,1233 r0 bottom value="60 V"
Q32 "MMBTA05LT1G" SOT-23 2064,538.13 r90 top value="60 V"
Q33 "DMG1013UW-7" SOT-323 1351,986 r0 bottom value=-20V
Q34 "MMBTA56LT1G" SOT-23 2155,1212 r270 bottom value="80 V"
Q35 "MMBTA56LT1G" SOT-23 2166,565.6 r90 bottom value="80 V"
Q36 "CSD19536KTT" KTT0002A_N 4650,1335.64 r270 top value=100V
Q37 "CSD19536KTT" KTT0002A_N 3825.33,1335.64 r270 top value=100V
Q38 "CSD19536KTT" KTT0002A_N 3413,1335.64 r270 top value=100V
Q39 "CSD19536KTT" KTT0002A_N 4237.67,1335.64 r270 top value=100V
Q40 "SI7439DP-T1-E3" PowerPAK_SO-8 4663,577 r270 bottom value=-150V
Q41 "SI2325DS-T1-E3" SOT-23 2509,939 r0 bottom value=-150V
Q42 "CSD19536KTT" KTT0002A_N 4237.67,643.31 r90 top value=100V
Q43 "CSD19536KTT" KTT0002A_N 3413,643.31 r90 top value=100V
Q44 "CSD19536KTT" KTT0002A_N 4650,643.31 r90 top value=100V
Q45 "CSD19536KTT" KTT0002A_N 3825.33,643.31 r90 top value=100V
Q46 "FMMT495TA" SOT-23 2780,1072 r180 bottom value="150 V"
Q47 "CPH3461-TL-W" SOT-23 3175,410 r0 bottom value=250V
Q48 "2N7002W-7-F" SOT-323 3856.41,313.4 r90 top value=60V
Q49 "DMG1013UW-7" SOT-323 3494,464 r270 bottom value=-20V
R1 "CRCW120680R6FKEA" 1206 305,777.71 r0 bottom value=80.6
R2 "CRCW120680R6FKEA" 1206 305,777.71 r0 top value=80.6
R3 "CRCW120680R6FKEA" 1206 305,898.47 r0 bottom value=80.6
R4 "CRCW120680R6FKEA" 1206 305,898.47 r0 top value=80.6
R5 "CRCW120680R6FKEA" 1206 305,1019.23 r0 bottom value=80.6
R6 "CRCW120680R6FKEA" 1206 305,1019.23 r0 top value=80.6
R7 "CRCW120680R6FKEA" 1206 305,1139.99 r0 bottom value=80.6
R8 "CRCW120680R6FKEA" 1206 305,1139.99 r0 top value=80.6
R9 "CRCW120680R6FKEA" 1206 305,1260.75 r0 bottom value=80.6
R10 "CRCW120680R6FKEA" 1206 305,1260.75 r0 top value=80.6
R11 "CRCW120680R6FKEA" 1206 305,1381.51 r0 bottom value=80.6
R12 "CRCW120680R6FKEA" 1206 305,1381.51 r0 top value=80.6
R13 "CRCW120680R6FKEA" 1206 305,1502.26 r0 bottom value=80.6
R14 "CRCW120680R6FKEA" 1206 305,1502.26 r0 top value=80.6
R15 "CRCW120680R6FKEA" 1206 305,1623.02 r0 bottom value=80.6
R16 "CRCW120680R6FKEA" 1206 305,1623.02 r0 top value=80.6
R17 "CRCW120680R6FKEA" 1206 305,1743.78 r0 bottom value=80.6
R18 "CRCW120680R6FKEA" 1206 305,1743.78 r0 top value=80.6
R19 "CRCW120680R6FKEA" 1206 305,1864.54 r0 bottom value=80.6
R20 "CRCW120680R6FKEA" 1206 305,1864.54 r0 top value=80.6
R21 "CRCW0603100RFKEA" 0603 614,739 r0 top value=100
R22 "CRCW0603300RJNEA" 0603 614,800.15 r0 top value=300
R23 "CRCW0603100RFKEA" 0603 614,861.3 r0 top value=100
R24 "CRCW0603300RJNEA" 0603 614,922.45 r0 top value=300
R25 "CRCW0603100RFKEA" 0603 614,983.6 r0 top value=100
R26 "CRCW0603300RJNEA" 0603 614,1044.75 r0 top value=300
R27 "CRCW0603100RFKEA" 0603 614,1105.9 r0 top value=100
R28 "CRCW0603300RJNEA" 0603 614,1167.05 r0 top value=300
R29 "CRCW0603100RFKEA" 0603 614,1228.2 r0 top value=100
R30 "CRCW0603300RJNEA" 0603 614,1289.35 r0 top value=300
R31 "CRCW0603100RFKEA" 0603 614,1350.5 r0 top value=100
R32 "CRCW0603300RJNEA" 0603 614,1411.65 r0 top value=300
R33 "CRCW0603100RFKEA" 0603 614,1472.8 r0 top value=100
R34 "CRCW0603300RJNEA" 0603 614,1533.95 r0 top value=300
R35 "CRCW0603100RFKEA" 0603 614,1595.1 r0 top value=100
R36 "CRCW0603300RJNEA" 0603 614,1656.25 r0 top value=300
R37 "CRCW0603100RFKEA" 0603 614,1717.4 r0 top value=100
R38 "CRCW0603300RJNEA" 0603 614,1778.55 r0 top value=300
R39 "CRCW0603100RFKEA" 0603 614,1839.7 r0 top value=100
R40 "CRCW0603300RJNEA" 0603 614,1900.85 r0 top value=300
R41 "CRCW060320R0FKEA" 0603 614,1962 r0 top value=20.0
R42 "CRCW120680R6FKEA" 1206 1325.49,1710 r270 top value=80.6
R43 "CRCW120680R6FKEA" 1206 1325.49,1710 r270 bottom value=80.6
R44 "CRCW120680R6FKEA" 1206 1446.25,1710 r270 top value=80.6
R45 "CRCW120680R6FKEA" 1206 1446.25,1710 r270 bottom value=80.6
R46 "CRCW120680R6FKEA" 1206 1567.01,1710 r270 top value=80.6
R47 "CRCW120680R6FKEA" 1206 1567.01,1710 r270 bottom value=80.6
R48 "CRCW120680R6FKEA" 1206 1687.77,1710 r270 top value=80.6
R49 "CRCW120680R6FKEA" 1206 1687.77,1710 r270 bottom value=80.6
R50 "CRCW120680R6FKEA" 1206 1808.53,1710 r270 top value=80.6
R51 "CRCW120680R6FKEA" 1206 1808.53,1710 r270 bottom value=80.6
R52 "CRCW120680R6FKEA" 1206 1929.29,1710 r270 top value=80.6
R53 "CRCW120680R6FKEA" 1206 1929.29,1710 r270 bottom value=80.6
R54 "CRCW120680R6FKEA" 1206 2050.04,1710 r270 top value=80.6
R55 "CRCW120680R6FKEA" 1206 2050.04,1710 r270 bottom value=80.6
R56 "CRCW120680R6FKEA" 1206 2170.8,1710 r270 top value=80.6
R57 "CRCW120680R6FKEA" 1206 2170.8,1710 r270 bottom value=80.6
R58 "CRCW120680R6FKEA" 1206 2291.56,1710 r270 top value=80.6
R59 "CRCW120680R6FKEA" 1206 2291.56,1710 r270 bottom value=80.6
R60 "CRCW120680R6FKEA" 1206 2412.32,1710 r270 top value=80.6
R61 "CRCW120680R6FKEA" 1206 2412.32,1710 r270 bottom value=80.6
R62 "CRCW06030000Z0EA" 0603 1197.33,1971.93 r180 bottom value=0
R63 "CRCW06030000Z0EA" 0603 1230.05,1875 r90 bottom value=0
R64 "CRCW0603100RFKEA" 0603 1289.27,1402 r270 top value=100
R65 "CRCW0603300RJNEA" 0603 1350.39,1402 r270 top value=300
R66 "CRCW0603100RFKEA" 0603 1411.52,1402 r270 top value=100
R67 "CRCW0603300RJNEA" 0603 1472.64,1402 r270 top value=300
R68 "CRCW0603100RFKEA" 0603 1533.77,1402 r270 top value=100
R69 "CRCW0603300RJNEA" 0603 1594.9,1402 r270 top value=300
R70 "CRCW0603100RFKEA" 0603 1656.02,1402 r270 top value=100
R71 "CRCW0603300RJNEA" 0603 1717.15,1402 r270 top value=300
R72 "CRCW0603100RFKEA" 0603 1778.28,1402 r270 top value=100
R73 "CRCW0603300RJNEA" 0603 1839.4,1402 r270 top value=300
R74 "CRCW0603100RFKEA" 0603 1900.53,1402 r270 top value=100
R75 "CRCW0603300RJNEA" 0603 1961.65,1402 r270 top value=300
R76 "CRCW0603100RFKEA" 0603 2022.78,1402 r270 top value=100
R77 "CRCW0603300RJNEA" 0603 2083.91,1402 r270 top value=300
R78 "CRCW0603100RFKEA" 0603 2145.03,1402 r270 top value=100
R79 "CRCW0603300RJNEA" 0603 2206.16,1402 r270 top value=300
R80 "CRCW0603100RFKEA" 0603 2267.29,1402 r270 top value=100
R81 "CRCW0603300RJNEA" 0603 2328.41,1402 r270 top value=300
R82 "CRCW0603100RFKEA" 0603 2389.54,1402 r270 top value=100
R83 "CRCW0603300RJNEA" 0603 2450.66,1402 r270 top value=300
R84 "CRCW060320R0FKEA" 0603 2511.27,1402 r270 top value=20.0
R85 "CRCW060310K0FKEA" 0603 820,432 r0 top value=10.0k
R86 "CRCW060310M0JNEA" 0603 1279.7,548 r270 top value=10Meg
R87 "CRCW060310K0FKEA" 0603 944,532 r0 top value=10.0k
R88 "CRCW0603100RFKEA" 0603 339,1977.23 r0 top value=100
R89 "RC0603FR-072ML" 0603 1271.7,642 r0 top value=2.00Meg
R90 "CRCW0603100RFKEA" 0603 2537.33,1675 r270 top value=100
R91 "CRCW060310M0JNEA" 0603 1160,745 r0 top value=10Meg
R92 "CRCW0603499KFKEA" 0603 1132,1058 r90 bottom value=499k
R93 "CRCW0603499KFKEA" 0603 1606.52,924 r0 top value=499k
R94 "CRCW060310K0FKEA" 0603 1070,1387 r90 bottom value=10.0k
R95 "CRCW060310K0FKEA" 0603 2174,923 r180 bottom value=10.0k
R96 "CRCW060310K0FKEA" 0603 2165.8,995.97 r180 top value=10.0k
R97 "CRCW0603100RFKEA" 0603 1882.88,721.65 r270 top value=100
R98 "CRCW0603100RFKEA" 0603 1824.91,721.65 r270 top value=100
R99 "RC0603FR-074K7L" 0603 1615,793 r90 bottom value=4.70k
R100 "CRCW060310M0JNEA" 0603 1057,1695 r270 top value=10Meg
R101 "CRCW060310M0JNEA" 0603 2166,833 r0 top value=10Meg
R102 "CRCW0603100RFKEA" 0603 1061.78,891 r90 top value=100
R103 "CRCW0603100RFKEA" 0603 996.28,891 r90 top value=100
R104 "RC0603FR-074K7L" 0603 1672,793 r90 bottom value=4.70k
R105 "CRCW0603100RFKEA" 0603 1114,1695 r90 top value=100
R106 "CRCW0603100RFKEA" 0603 2166,892 r0 top value=100
R107 "RC1206FR-07619RL" 1206 805,1838 r180 bottom value=619
R108 "AC1206FR-07154RL" 1206 2515.33,1447 r90 bottom value=154
R109 "AC1206FR-07154RL" 1206 2515.33,1642 r90 bottom value=154
R110 "CRCW060310K0FKEA" 0603 908.6,1147 r90 bottom value=10.0k
R111 "RC1206FR-07619RL" 1206 805,1935 r180 bottom value=619
R112 "RC2512JK-07200RL" 2512 1468,824 r90 top value=200
R113 "RC0603FR-072KL" 0603 617,1170 r90 bottom value=2.00k
R114 "CRCW0603150KFKEA" 0603 1243,1113 r90 bottom value=150k
R115 "CRCW0603200KFKEA" 0603 1493,1114 r180 bottom value=200k
R116 "CRCW060380K6FKEA" 0603 1688.44,1064 r270 bottom value=80.6k
R117 "RC0603FR-07300RL" 0603 1750,1064 r270 bottom value=300
R118 "RC2512JK-07200RL" 2512 737,1466 r0 bottom value=200
R119 "CRCW0603200KFKEA" 0603 948,432 r0 top value=200k
R120 "CRCW06030000Z0EA" 0603 873,392 r270 bottom value=0
R121 "CRCW0603330KJNEA" 0603 1798,1196.65 r270 bottom value=330k
R122 "CRCW0603200KFKEA" 0603 1468.7,548 r270 top value=200k
R123 "RC0603FR-0733KL" 0603 1536.7,548 r90 top value=33.0k
R124 "CRCW0603200KFKEA" 0603 1564.54,687 r270 top value=200k
R125 "CRCW060326K1FKEA" 0603 1767,721.65 r90 top value=26.1k
R126 "RC0603FR-0710RL" 0603 1515,897.07 r0 bottom value=10.0
R127 "CRCW0603200KFKEA" 0603 823,549 r90 bottom value=200k
R128 "CRCW0603150KFKEA" 0603 1243,1244 r270 bottom value=150k
R129 "CRCW0603200KFKEA" 0603 1491,1173 r180 bottom value=200k
R130 "CRCW060380K6FKEA" 0603 2248,1184 r270 bottom value=80.6k
R131 "RC0603FR-07300RL" 0603 2309,1183 r270 bottom value=300
R132 "CRCW0603150KFKEA" 0603 2158,529 r90 top value=150k
R133 "CRCW0603200KFKEA" 0603 2259,552 r90 bottom value=200k
R134 "CRCW060380K6FKEA" 0603 2046,574 r180 bottom value=80.6k
R135 "RC0603FR-07300RL" 0603 2046,519 r180 bottom value=300
R136 "CRCW0603150KFKEA" 0603 1978.3,1196.65 r270 bottom value=150k
R137 "RC0603FR-0710RL" 0603 1343,897 r180 bottom value=10.0
R138 "CRCW0603150KFKEA" 0603 2076.87,715 r90 bottom value=150k
R139 "RC0603FR-07499RL" 0603 3123,1531 r0 bottom value=499
R140 "CRCW060310M0JNEA" 0603 3272,1688.78 r180 top value=10Meg
R141 "CRCW060375R0FKEA" 0603 4690,1647 r270 top value=75.0
R142 "CRCW060375R0FKEA" 0603 3867.33,1647 r270 top value=75.0
R143 "CRCW060375R0FKEA" 0603 3456,1647 r270 top value=75.0
R144 "CRCW060375R0FKEA" 0603 4278.67,1647 r270 top value=75.0
R145 "RT0603BRD0749K9L" 0603 4346,566 r0 bottom value=49.9k
R146 "CRCW06031M00JNEA" 0603 4435,596.5 r270 bottom value=1.0Meg
R147 "CRCW080510R0FKEA" 0805_HV 2243,1010 r180 bottom value=10.0
R148 "CRCW060310M0JNEA" 0603 2288,912 r90 bottom value=10Meg
R149 "NC" 0603 2641,1056 r0 bottom value=390
R150 "RC1206FR-07511RL" 1206 4710.5,302.3 r270 bottom value=511
R151 "RC1206FR-07511RL" 1206 4809,302.3 r270 bottom value=511
R152 "RC1206FR-07511RL" 1206 4513.5,302.3 r270 bottom value=511
R153 "RC1206FR-07511RL" 1206 4612,302.3 r270 bottom value=511
R154 "RC1206FR-07511RL" 1206 4415,302.3 r270 bottom value=511
R155 "RC0805JR-0756KL" 0805_HV 2241,809.31 r180 bottom value=56k
R156 "NC" 0603 2640.98,1002 r0 bottom value=806
R157 "AC0805FR-07806RL" 0805_HV 2652,926 r180 bottom value=806
R158 "CRCW060375R0FKEA" 0603 4196.2,324.5 r270 top value=75.0
R159 "CRCW060375R0FKEA" 0603 3369,324.5 r270 top value=75.0
R160 "CRCW060375R0FKEA" 0603 4609.8,324.5 r270 top value=75.0
R161 "CRCW060375R0FKEA" 0603 3782.6,324.5 r270 top value=75.0
R162 "RC0603FR-0747RL" 0603 2028.78,288 r0 top value=47.0
R163 "NC" 0603 2343,771 r90 bottom value=10M
R164 "CRCW06030000Z0EA" 0603 2773,946 r90 bottom value=NC
R165 "CRCW060310M0JNEA" 0603 3067,342 r90 bottom value=10Meg
R166 "RC0805JR-0756KL" 0805_HV 3299.5,479 r0 bottom value=56k
R167 "CRCW060310M0JNEA" 0603 4036.5,354 r180 top value=10Meg
R168 "CRCW0805100RFKEA" 0805_HV 3239,314 r270 bottom value=100
R169 "RC0603FR-07620KL" 0603 2878,955 r0 bottom value=620k
R170 "CRCW06035K10JNEA" 0603 2937.51,1085 r0 top value=5.1k
R171 "AC0805JR-071K5L" 0805_HV 3823,340 r0 bottom value=1.5k
R172 "CRCW06035K10JNEA" 0603 3064,721.5 r270 top value=5.1k
R173 "CRCW060310K0FKEA" 0603 3033,342 r0 top value=10.0k
R174 "CRCW060310M0JNEA" 0603 3838,425 r180 top value=10Meg
R175 "CRCW0603806RFKEA" 0603 3487,289 r0 top value=806
R176 "CRCW06035K10JNEA" 0603 3064,594 r270 top value=5.1k
R177 "RC0603FR-07604KL" 0603 3124,593 r270 top value=604k
R178 "RC0603FR-0768KL" 0603 931,79 r270 bottom value=68.0k
R179 "CRCW060310K0FKEA" 0603 767,132 r0 bottom value=10.0k
R180 "CRCW0603100RFKEA" 0603 947.94,332.83 r180 top value=100
R181 "CRCW0603100RFKEA" 0603 1350,1178.73 r90 top value=100
R182 "CRCW0603100RFKEA" 0603 622,528 r0 bottom value=100
R183 "CRCW0603100RFKEA" 0603 622,585.47 r180 bottom value=100
R184 "CRCW0603100RFKEA" 0603 670.35,447.55 r90 bottom value=100
R185 "CRCW0603100RFKEA" 0603 1289.06,1178.73 r90 top value=100
R186 "CRCW0603100RFKEA" 0603 820,352 r0 top value=100
R187 "CRCW0603100RFKEA" 0603 311,398 r180 bottom value=100
R188 "CRCW0603100RFKEA" 0603 311,455.3 r180 bottom value=100
R189 "RC0603FR-07499RL" 0603 467.2,79 r270 bottom value=499
R190 "RC0603FR-07499RL" 0603 535.2,79 r270 bottom value=499
R191 "RC0603FR-07499RL" 0603 603.2,79 r270 bottom value=499
R192 "CRCW0603100RFKEA" 0603 1104,800 r180 bottom value=100
R193 "CRCW0603100RFKEA" 0603 645,164 r180 bottom value=100
R194 "CRCW0603100RFKEA" 0603 645,285 r180 bottom value=100
R195 "CRCW0603100RFKEA" 0603 1104,740 r180 bottom value=100
R196 "CRCW0603100RFKEA" 0603 820,285 r180 top value=100
R197 "CRCW0603100RFKEA" 0603 645,224.5 r180 bottom value=100
R198 "RC0603FR-0747KL" 0603 325,473.85 r270 top value=47.0k
R199 "RC0603FR-074K7L" 0603 429.5,669 r180 top value=4.70k
R200 "RC0603FR-074K7L" 0603 429.5,612 r180 top value=4.70k
R201 "CRCW0603100RFKEA" 0603 969,153 r180 top value=100
R202 "CRCW0603100RFKEA" 0603 969,210 r180 top value=100
R203 "CRCW060310K0FKEA" 0603 969,96.6 r0 top value=10.0k
R204 "CRCW060310K0FKEA" 0603 969,40 r0 top value=10.0k
R205 "RC0603FR-0760R4L" 0603 2057,156 r90 top value=60.4
R206 "RC0603FR-0760R4L" 0603 1996,156 r270 top value=60.4
R207 "CRCW060310K0FKEA" 0603 728.79,447.55 r270 bottom value=10.0k
R208 "RC0603FR-07120RL" 0603 1378,173 r90 top value=120
R209 "CRCW0603100RFKEA" 0603 2630.33,1778 r180 bottom value=100
R210 "CRCW060382K5FKEA" 0603 2692.95,1667 r180 bottom value=82.5k
R211 "CRCW04020000Z0ED" 0402 2977.33,1504 r0 bottom value=0
R212 "RC0603FR-07499KL" 0603 2926.33,1541 r270 top value=NC
R213 "RC0402FR-07523KL" 0402 2977.33,1415 r0 bottom value=523k
R214 "CRCW060363K4FKEA" 0603 2865.33,1667.07 r0 bottom value=63.4k
R215 "CRCW0603200KFKEA" 0603 2914.33,1294.7 r180 bottom value=200k
R216 "CRCW06030000Z0EA" 0603 2173,408 r180 bottom value=0
R217 "CRCW06030000Z0EA" 0603 2353,506 r0 bottom value=0
R218 "RC0603FR-0710RL" 0603 2515.33,1976.52 r180 top value=10.0
R219 "CSNL2512FT2L00" 2512 2774.28,452.46 r270 top value=0.002
R220 "CSNL2512FT2L00" 2512 2774.28,452.46 r270 bottom value=0.002
R221 "CSNL2512FT2L00" 2512 2634.5,452.46 r270 top value=0.002
R222 "CSNL2512FT2L00" 2512 2634.5,452.46 r270 bottom value=0.002
RT1 "MF51E103F3950" Thermistor_103AT-2 185.5,623.5 r90 top value="10.0k ohm"
RT2 "MF51E103F3950" Thermistor_103AT-2 1801,561 r90 top value="10.0k ohm"
RT3 "MF51E103F3950" Thermistor_103AT-2 304,623.5 r90 top value="10.0k ohm"
RT4 "MF51E103F3950" Thermistor_103AT-2 1697,561 r90 top value="10.0k ohm"
RT5 "MF51E103F3950" Thermistor_103AT-2 67,623.5 r90 top value="10.0k ohm"
RT6 "MF51E103F3950" Thermistor_103AT-2 1938,561 r90 top value="10.0k ohm"
RT7 "TMP6131DECR" DEC0002A 614,470 r0 bottom
S1 "RS-032G05A3-SM RT" SW_RS-032G05A3-SM 171,332 r270 top
U1 "BQ76942PFBR" PFB0048A_N 1018,1348 r0 top
U2 "BQ76942PFBR" PFB0048A_N 1896.38,1013.63 r270 top
U3 "ISO1640BDR" D0008A-MFG 1429,708 r0 bottom
U4 "TPS7A2501DRVR" DRV0006A 1945,365 r90 bottom
U5 "MSP430FR2155TDBTR" DBT0038A_N 601,380.65 r0 top
U6 "TCAN1042HVDRQ1" D0008A_L 1795,174 r0 top
U7 "THVD1400D" D0008B-MFG 1203,183.84 r0 top
U8 "TPD2E007DCKR" DCK0003A_N 1500,178 r0 top
U9 "LM5168PDDAR" DDA0008E_M 2779.33,1528 r0 bottom

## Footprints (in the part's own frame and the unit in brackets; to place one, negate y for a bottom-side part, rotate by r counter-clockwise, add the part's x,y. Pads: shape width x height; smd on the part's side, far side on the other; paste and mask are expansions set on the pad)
0402 [mm] "0402 from SM-752 data"
  rect 0.8x0.6 smd: 1(-0.6,0) 2(0.6,0)
  silkscreen extent -1.22,-0.52 1.22,0.52, body extent -0.55,-0.3 0.55,0.3, height 0.6
0603 [mm] "0603 from SM-752 data"
  rect 1x0.95 smd: 1(-0.8,0) 2(0.8,0)
  silkscreen extent -1.52,-0.69 1.52,0.69, body extent -0.87,-0.47 0.87,0.47, height 1
0603S [mil]
  rect 20x35 smd: 1(-30,0) 2(30,0)
  silkscreen extent -10,-17 10,17, body extent -34,-19 34,19, height 39
0805_HV [mil] "0805 with 30mil clearance between pads"
  rect 50x63 smd: 1(-40,0) 2(40,0)
  silkscreen extent -74,-40 74,40, body extent -43,-29 43,29, height 57
1206 [mm] "1206 from SM-752 data"
  rect 1.3x1.85 smd: 1(-1.45,0) 2(1.45,0)
  silkscreen extent -2.4,-1.21 2.4,1.21, body extent -1.7,-0.9 1.7,0.9, height 1.35
1206_180 [mm] "1206_180"
  rect 1.1x1.6 smd: 1(-1.7,0) 2(1.7,0)
  silkscreen extent -0.9,-1 0.9,1, body extent -1.75,-0.95 1.75,0.95, height 1.8
1206_190 [mm] "1206_190"
  rect 1.1x1.6 smd: 1(-1.7,0) 2(1.7,0)
  silkscreen extent -0.9,-1 0.9,1, body extent -1.75,-0.95 1.75,0.95, height 1.9
1210 [mm] "1210 from SM-752 data"
  rect 1.3x2.7 smd: 1(-1.45,0) 2(1.45,0)
  silkscreen extent -2.32,-1.57 2.32,1.57, body extent -1.7,-1.35 1.7,1.35, height 1.35
2512 [mm] "Chip Resistor, Body 6.3x3.2mm, IPC Medium Density"
  rect 1.3x3.4 smd: 1(-2.95,0) 2(2.95,0)
  silkscreen extent -1.9,-1.6 1.9,1.6, body extent -3.22,-1.67 3.22,1.67, height 0.71
0325030 [mm]
  round 1.9 hole 1.15: 1(-2,-3.5) 2(35.8,-3.5)
  silkscreen extent 0,-7 33.8,0
D0008A-MFG [mm]
  rrect17% 1.55x0.6 smd paste+0 mask+0: 1(-2.7,1.905) 2(-2.7,0.635) 3(-2.7,-0.635) 4(-2.7,-1.905) 5(2.7,-1.905) 6(2.7,-0.635) 7(2.7,0.635) 8(2.7,1.905)
  silkscreen extent -4.17,-2.5 1.5,2.5, body extent -3,-2.45 3,2.45, height 1.75
D0008A_L [mm] "SOIC, 8-Leads, Body 4.9x3.9mm, Pitch 1.27mm, IPC High Density"
  oval 1.25x0.55 smd: 1(-2.625,1.905) 2(-2.625,0.635) 3(-2.625,-0.635) 4(-2.625,-1.905) 5(2.625,-1.905) 6(2.625,-0.635) 7(2.625,0.635) 8(2.625,1.905)
  silkscreen extent -3.1,-2.5 0.9,2.5, body extent -3,-2.45 3,2.45, height 1.63
D0008B-MFG [mm]
  rrect17% 1.4x0.6 smd paste+0 mask+0: 1(-2.75,1.905) 2(-2.75,0.635) 3(-2.75,-0.635) 4(-2.75,-1.905) 5(2.75,-1.905) 6(2.75,-0.635) 7(2.75,0.635) 8(2.75,1.905)
  silkscreen extent -4.14,-2.5 1.5,2.5, body extent -3.55,-2.75 3.55,2.75, height 0.25
DBT0038A_N [mm] "TSSOP, 38-Leads, Body 9.7x4.4mm, Pitch 0.5mm, IPC Medium Density"
  oval 1.4x0.3 smd: 1(-2.95,4.5) 2(-2.95,4) 3(-2.95,3.5) 4(-2.95,3) 5(-2.95,2.5) 6(-2.95,2) 7(-2.95,1.5) 8(-2.95,1) 9(-2.95,0.5) 10(-2.95,0) 11(-2.95,-0.5) 12(-2.95,-1) 13(-2.95,-1.5) 14(-2.95,-2) 15(-2.95,-2.5) 16(-2.95,-3) 17(-2.95,-3.5) 18(-2.95,-4) 19(-2.95,-4.5) 20(2.95,-4.5) 21(2.95,-4) 22(2.95,-3.5) 23(2.95,-3) 24(2.95,-2.5) 25(2.95,-2) 26(2.95,-1.5) 27(2.95,-1) 28(2.95,-0.5) 29(2.95,0) 30(2.95,0.5) 31(2.95,1) 32(2.95,1.5) 33(2.95,2) 34(2.95,2.5) 35(2.95,3) 36(2.95,3.5) 37(2.95,4) 38(2.95,4.5)
  silkscreen extent -3.5,-4.9 1.5,4.9, body extent -3.21,-4.85 3.21,4.85, height 1.2
DCK0003A_N [mm] "SOT23, 3-Leads, Body 2.0x1.25mm, Pitch 0.65mm, Lead Span 2.1mm, IPC Medium Density"
  rrect25% 0.85x0.4 smd: 1(-1.125,0.65) 2(-1.125,-0.65) 3(1.125,0)
  silkscreen extent -1.48,-1.1 0.7,1.1, body extent -1.06,-1 1.06,1, height 1.1
DDA0008E_M [mm]
  rrect15% 1.65x0.65 smd: 1(-2.825,1.905) 2(-2.825,0.635) 3(-2.825,-0.635) 4(-2.825,-1.905) 5(2.825,-1.905) 6(2.825,-0.635) 7(2.825,0.635) 8(2.825,1.905)
  rrect7% 2.95x4.9 smd paste-1.5 mask-1.5: 9(0,0)
  rrect4% 2.4x3.1 on Bottom Paste: 9(0,0)
  rrect4% 2.4x3.1 on Bottom Solder: 9(0,0)
  silkscreen extent -3.42,-2.52 1.4,2.5, body extent -3,-2.45 3,2.45, height 1.57
DEC0002A [mm] "X1SON-2"
  rrect57% 0.35x0.6 smd paste-0.5 mask-0.05: 1(-0.325,0) 2(0.325,0)
  rrect33% 0.3x0.5 on Bottom Paste: 1S(-0.35,0) 2S(0.35,0)
  body extent -0.5,-0.3 0.5,0.3, height 0.5
DRV0006A [mm] "SON, 6-Leads, Body 2x2mm, Pitch 0.65mm, Thermal Pad 1.6x1mm, TI Recommended"
  rrect33% 0.45x0.3 smd: 1(-0.975,0.65) 2(-0.975,0) 3(-0.975,-0.65) 4(0.975,-0.65) 5(0.975,0) 6(0.975,0.65)
  rrect14% 1x0.7 on Bottom Paste: 7(0,-0.45) 7(0,0.45)
  rrect10% 1x1.6 smd paste-0.5: 7(0,0)
  silkscreen extent -1.05,-1.2 1.05,1.2, body extent -1.05,-1.05 1.05,1.05, height 0.81
HDR1X2 [mm] "Connector; Header; 2 Position"
  rect 1.5x1.5 hole 0.9: 1(0,0)
  round 1.5 hole 0.9: 2(2.54,0)
  silkscreen extent -1.27,-1.27 3.81,1.27
HDR1X4 [mm] "Connector; Header; 4 Position"
  rect 1.5x1.5 hole 0.9: 1(0,0)
  round 1.5 hole 0.9: 2(2.54,0) 3(5.08,0) 4(7.62,0)
  silkscreen extent -1.27,-1.27 8.89,1.27
HDR2X2 [mm] "Connector; Header; 2x2 Position"
  rect 1.5x1.5 hole 0.9: 1(0,0)
  round 1.5 hole 0.9: 2(0,2.54) 3(2.54,0) 4(2.54,2.54)
  silkscreen extent -1.27,-1.27 3.81,3.81
KTT0002A_N [mm] "D2-PAK, 2-Leads, Body 9x10.1mm, Pitch 2.54mm, Lead Span 15.1mm, IPC Medium Density"
  rrect10% 3.5x1 smd: 1(-6.15,2.54) 3(-6.15,-2.54)
  rrect1% 8.4x8.65 smd paste-4.2: 2(3.75,0)
  silkscreen extent -7.75,-5.07 -1.78,5.07, body extent -6.68,-5.08 7.62,5.08, height 4.72
PFB0048A_N [mm] "Thin QFP, 48-Leads, Body 7x7mm, Pitch 0.5mm, IPC Medium Density"
  oval 1.45x0.3 smd: 1(-4.225,2.75) 2(-4.225,2.25) 3(-4.225,1.75) 4(-4.225,1.25) 5(-4.225,0.75) 6(-4.225,0.25) 7(-4.225,-0.25) 8(-4.225,-0.75) 9(-4.225,-1.25) 10(-4.225,-1.75) 11(-4.225,-2.25) 12(-4.225,-2.75) 25(4.225,-2.75) 26(4.225,-2.25) 27(4.225,-1.75) 28(4.225,-1.25) 29(4.225,-0.75) 30(4.225,-0.25) 31(4.225,0.25) 32(4.225,0.75) 33(4.225,1.25) 34(4.225,1.75) 35(4.225,2.25) 36(4.225,2.75)
  oval 0.3x1.45 smd: 13(-2.75,-4.225) 14(-2.25,-4.225) 15(-1.75,-4.225) 16(-1.25,-4.225) 17(-0.75,-4.225) 18(-0.25,-4.225) 19(0.25,-4.225) 20(0.75,-4.225) 21(1.25,-4.225) 22(1.75,-4.225) 23(2.25,-4.225) 24(2.75,-4.225) 37(2.75,4.225) 38(2.25,4.225) 39(1.75,4.225) 40(1.25,4.225) 41(0.75,4.225) 42(0.25,4.225) 43(-0.25,4.225) 44(-0.75,4.225) 45(-1.25,4.225) 46(-1.75,4.225) 47(-2.25,4.225) 48(-2.75,4.225)
  silkscreen extent -4.17,-2.75 2.75,3.57, body extent -4.5,-4.5 4.5,4.5, height 1.07
PowerPAK_SO-8 [mil] "Vishay PowerPAK SO-8, Body 5.3x6.0mm (max), Pitch 1.27mm, IPC Medium Density"
  rect 50x24 smd mask+2.99: 1(-109.5,75) 2(-109.5,25) 3(-109.5,-25) 4(-109.5,-75)
  rect 48x24 smd mask+2.99: 5(109.5,-75) 8(109.5,75)
  rect 48x24 smd paste-12 mask+2.99: 6(109.5,-25) 7(109.5,25)
  rect 150x154 smd paste-75 mask+2.99: 9(22.5,0)
  silkscreen extent -130,-104 59,104, body extent -121,-102 121,101, height 43
SMC [mil] "Molded Diode, 2-Leads, Body 6.9x5.8mm, IPC Medium Density, based on OnSemi component dimensions and land patterns"
  rect 110x150 smd: 1(-140.49,0) 2(140.49,0)
  silkscreen extent -221,-124 189,123, body extent -156,-116 156,116, height 91
SOD-123 [mm] "On Semi recommended land pattern"
  rect 0.915x1.22 smd: 1(-1.637,0) 2(1.637,0)
  silkscreen extent -2.74,-1.17 2.03,1.17, body extent -1.93,-0.9 1.93,0.9, height 1.35
SOD-323 [mm] "NXP recommended land pattern"
  rect 0.6x0.6 smd paste-0.05: 1(-1.1,0) 2(1.1,0)
  silkscreen extent -2.06,-0.86 1.53,0.86, body extent -1.3,-0.67 1.3,0.68, height 1.1
SOD-323F [mm] "NXP recommended land pattern"
  rect 0.6x0.6 smd paste-0.05: 1(-1.1,0) 2(1.1,0)
  silkscreen extent -2.13,-0.86 1.53,0.86, body extent -1.35,-0.68 1.35,0.67, height 0.79
SOD-523 [mm] "NXP Semiconductor recommended land pattern, nominal STEP model"
  rect 0.8x0.6 smd paste-0.05: 1(-0.55,0) 2(0.55,0)
  silkscreen extent -1.65,-0.66 1.2,0.66, body extent -0.8,-0.4 0.8,0.4, height 0.72
SOT-23 [mm] "SOT23, 3-Leads, Body 2.9x1.3mm, Pitch 0.95mm, Lead Span 2.5mm, IPC Medium Density"
  rrect50% 1x0.6 smd: 1(-1.2,0.95) 2(-1.2,-0.95) 3(1.2,0)
  silkscreen extent -1.62,-1.5 0.7,1.5, body extent -1.16,-1.45 1.21,1.45, height 1
SOT-223 [mm] "SOT223/SC73, 4-Leads, Body 6.5x3.5mm, Pitch 2.3mm, Lead Span 7mm, IPC Medium Density"
  rrect10% 2.4x1 smd: 1(-2.9,2.3) 2(-2.9,0) 3(-2.9,-2.3)
  rrect4% 2.4x3.3 smd: 4(2.9,0)
  silkscreen extent -3.33,-3.35 1.4,3.35, body extent -3.5,-3.25 3.5,3.25, height 1.62
SOT-323 [mm] "Diodes Inc recommended land pattern.  2016-02-24"
  rrect21% 0.6x0.47 smd: 1(-0.95,0.65) 2(-0.95,-0.65) 3(0.95,0)
  silkscreen extent -1.14,-1.22 0.77,1.22, body extent -1.13,-1.13 1.12,1.12, height 1.13
SW_RS-032G05A3-SM [mm] "SMT, 2-Leads, Body 6x3.5mm, Pin Spacing 8mm"
  rect 2x2 smd: 1(-4,0) 2(4,0)
  silkscreen extent -3,-1.75 3,1.75, body extent -4,-1.75 4,1.75, height 4.3
Thermistor_103AT-2 [mil] "SEMITEC"
  rect 65x65 hole 35: 1(-50,0)
  round 65 hole 35: 2(50,0)
  body extent -78,-47 79,47, height 338
UUX_800x620 [mm] "SMD, 2-Leads, Dia 8mm"
  rect 4x2.5 smd: 1(-3.05,0) 2(3.05,0)
  silkscreen extent -4.25,-4.25 4.25,4.25, body extent -4.25,-4.25 4.25,4.25, height 6.51
WE-MAPI_3015 [mm] "SMD, 2-Leads, Body 3x3mm"
  rect 1.3x3.4 smd: 1(-1.05,0) 2(1.05,0)
  silkscreen extent -0.12,-1.7 0.12,1.7, body extent -1.6,-1.6 1.6,1.6, height 1.5
WE-PD_7345 [mm] "SMD Inductor, 2-Leads, Body 7,3x7,3mm"
  rect 1.6x2.2 smd: 1(-3.2,0) 2(3.2,0)
  silkscreen extent -3.65,-3.68 3.61,3.6, body extent -3.65,-3.68 3.65,3.6, height 4.49
WL-SMCW_RED [mm] "WURTH"
  rect 0.8x0.8 smd: 1(-0.8,0) 2(0.8,0)
  silkscreen extent -1.9,-0.8 1.2,0.8, body extent -0.85,-0.45 0.85,0.45, height 0.8
"XH Connector 11P" [mm]
  rect 1.5x1.5 hole 0.9: 1(0,0)
  round 1.5 hole 0.9: 2(0,-2.5) 3(0,-5) 4(0,-7.5) 5(0,-10) 6(0,-12.5) 7(0,-15) 8(0,-17.5) 9(0,-20) 10(0,-22.5) 11(0,-25)
  silkscreen extent -2.37,-27.5 3.37,2.5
